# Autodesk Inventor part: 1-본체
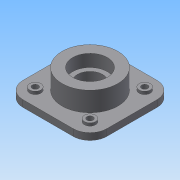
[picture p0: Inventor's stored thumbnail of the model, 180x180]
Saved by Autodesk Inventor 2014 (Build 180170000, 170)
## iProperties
Created: 2015-09
Part Number: 1-본체
Material: Generic
Document SubType Name: Modeling
Designer: study
Density: 1 g/cm^3
Appearance: Default
Author: study
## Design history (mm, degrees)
sketch "스케치1"
  geometry: L1 (75, -75)-(-75, -75); L2 (-75, -75)-(-75, 75); L3 (-75, 75)-(75, 75); L4 (75, 75)-(75, -75); 3 further points
  constraints: 8 end point, 1 coincident, 1 midpoint, 1 vertical alignment, 9 other
  dimensions: "d0" = 150 distance of L2.end L3.end
extrude "돌출1" new body sketch "스케치1" distance "d1" = 12; taper "d2" = 0 deg
fillet "모깎기1" dims "d3" = 30
sketch "스케치2"
  geometry: C1 r 50 at (0, 0); 1 further point
  constraints: 1 centre point, 1 coincident
  dimensions: "d4" = 100 diameter of C1
extrude "돌출2" join sketch "스케치2" distance "d5" = 23; taper "d6" = 0 deg
node "작업 평면1"
sketch "스케치3"
  geometry: C1 r 50 at (0, 0); 1 further point
  constraints: 1 centre point, 1 coincident
  dimensions: "d8" = 100 diameter of C1
extrude "돌출3" join sketch "스케치3" stored distance "d9" = 23; taper "d10" = 0 deg
hole "구멍1" diameter "d13" = 45; stored, may be unused: countersink angle "d17" = 90 deg, drill point angle "d19" = 0 deg; dims "d11" = 10, "d12" = 10, "d14" = 6, "d15" = 62, "d16" = 22, "d18" = 8
hole "구멍2" diameter "d22" = 45; stored, may be unused: countersink angle "d26" = 90 deg, drill point angle "d28" = 0 deg; dims "d20" = 10, "d21" = 10, "d23" = 6, "d24" = 62, "d25" = 22, "d27" = 8
node "작업 평면2"
sketch "스케치5"
  geometry: L1 (49, -49)-(-49, -49); L2 (-49, -49)-(-49, 49); L3 (-49, 49)-(49, 49); L4 (49, 49)-(49, -49); C1 r 10 at (-49, 49); C2 r 10 at (49, 49); C3 r 10 at (49, -49); C4 r 10 at (-49, -49); 3 further points
  constraints: 8 end point, 5 coincident, 4 centre point, 3 equal radius, 1 midpoint, 1 vertical alignment, 9 other
  dimensions: "d31" = 98 distance of L2.end L3.end; "d32" = 20 diameter of C1
extrude "돌출4" join sketch "스케치5" stored distance "d33" = 23; taper "d34" = 0 deg
sketch "스케치6"
  geometry: C1 r 10 at (0, 0) reference; C2 r 10 at (0, 98) reference; C3 r 10 at (-98, 98) reference; C4 r 10 at (-98, 0) reference; 5 further points
  constraints: 4 coincident
hole "구멍3" sketch "스케치6" at (0, 98), (0, 0), (-98, 0), (-98, 98) diameter "d35" = 11; stored, may be unused: countersink angle "d39" = 90 deg, drill point angle "d41" = 0 deg; dims "d36" = 6, "d37" = 62, "d38" = 22, "d40" = 8
node "솔리드1"
other parameters: "d30" = 5
